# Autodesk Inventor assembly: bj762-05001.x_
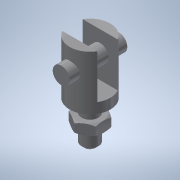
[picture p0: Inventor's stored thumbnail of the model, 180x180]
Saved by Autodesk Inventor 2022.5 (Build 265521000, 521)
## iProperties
Part Number: bj762-05001.x_
Material: 一般
Document SubType Name: Assembly
Designer: ImaoCorp
Sending System: SOLIDWORKS 2017-2017317
MC: AMD64
MC_MODEL: Intel64 Family 6 Model 60 Stepping 3, GenuineIntel
OS: Windows_NT
FRU: Parasolid Version 29.0, build 201,  4-17-2017
FORMAT: text
GUISE: transmit
KEY: bj762-05001
FILE: bj762-05001.x_t
DATE: Fri Mar 15 10:09:34 2019
Author: ImaoCorp
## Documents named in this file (3)
- X:\14_SW2022-Inv2022\00_全2023-1023新製品(TCC)まで\b\bj762-05001\BJ762-05001.iam
- X:\14_SW2022-Inv2022\00_全2023-1023新製品(TCC)まで\b\bj762-05001\bj762-05001_01.ipt
- X:\14_SW2022-Inv2022\00_全2023-1023新製品(TCC)まで\b\bj762-05001\bj762-05001_02.ipt
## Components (2 placed, 2 different names)
1. bj762-05001_01
2. bj762-05001_02
